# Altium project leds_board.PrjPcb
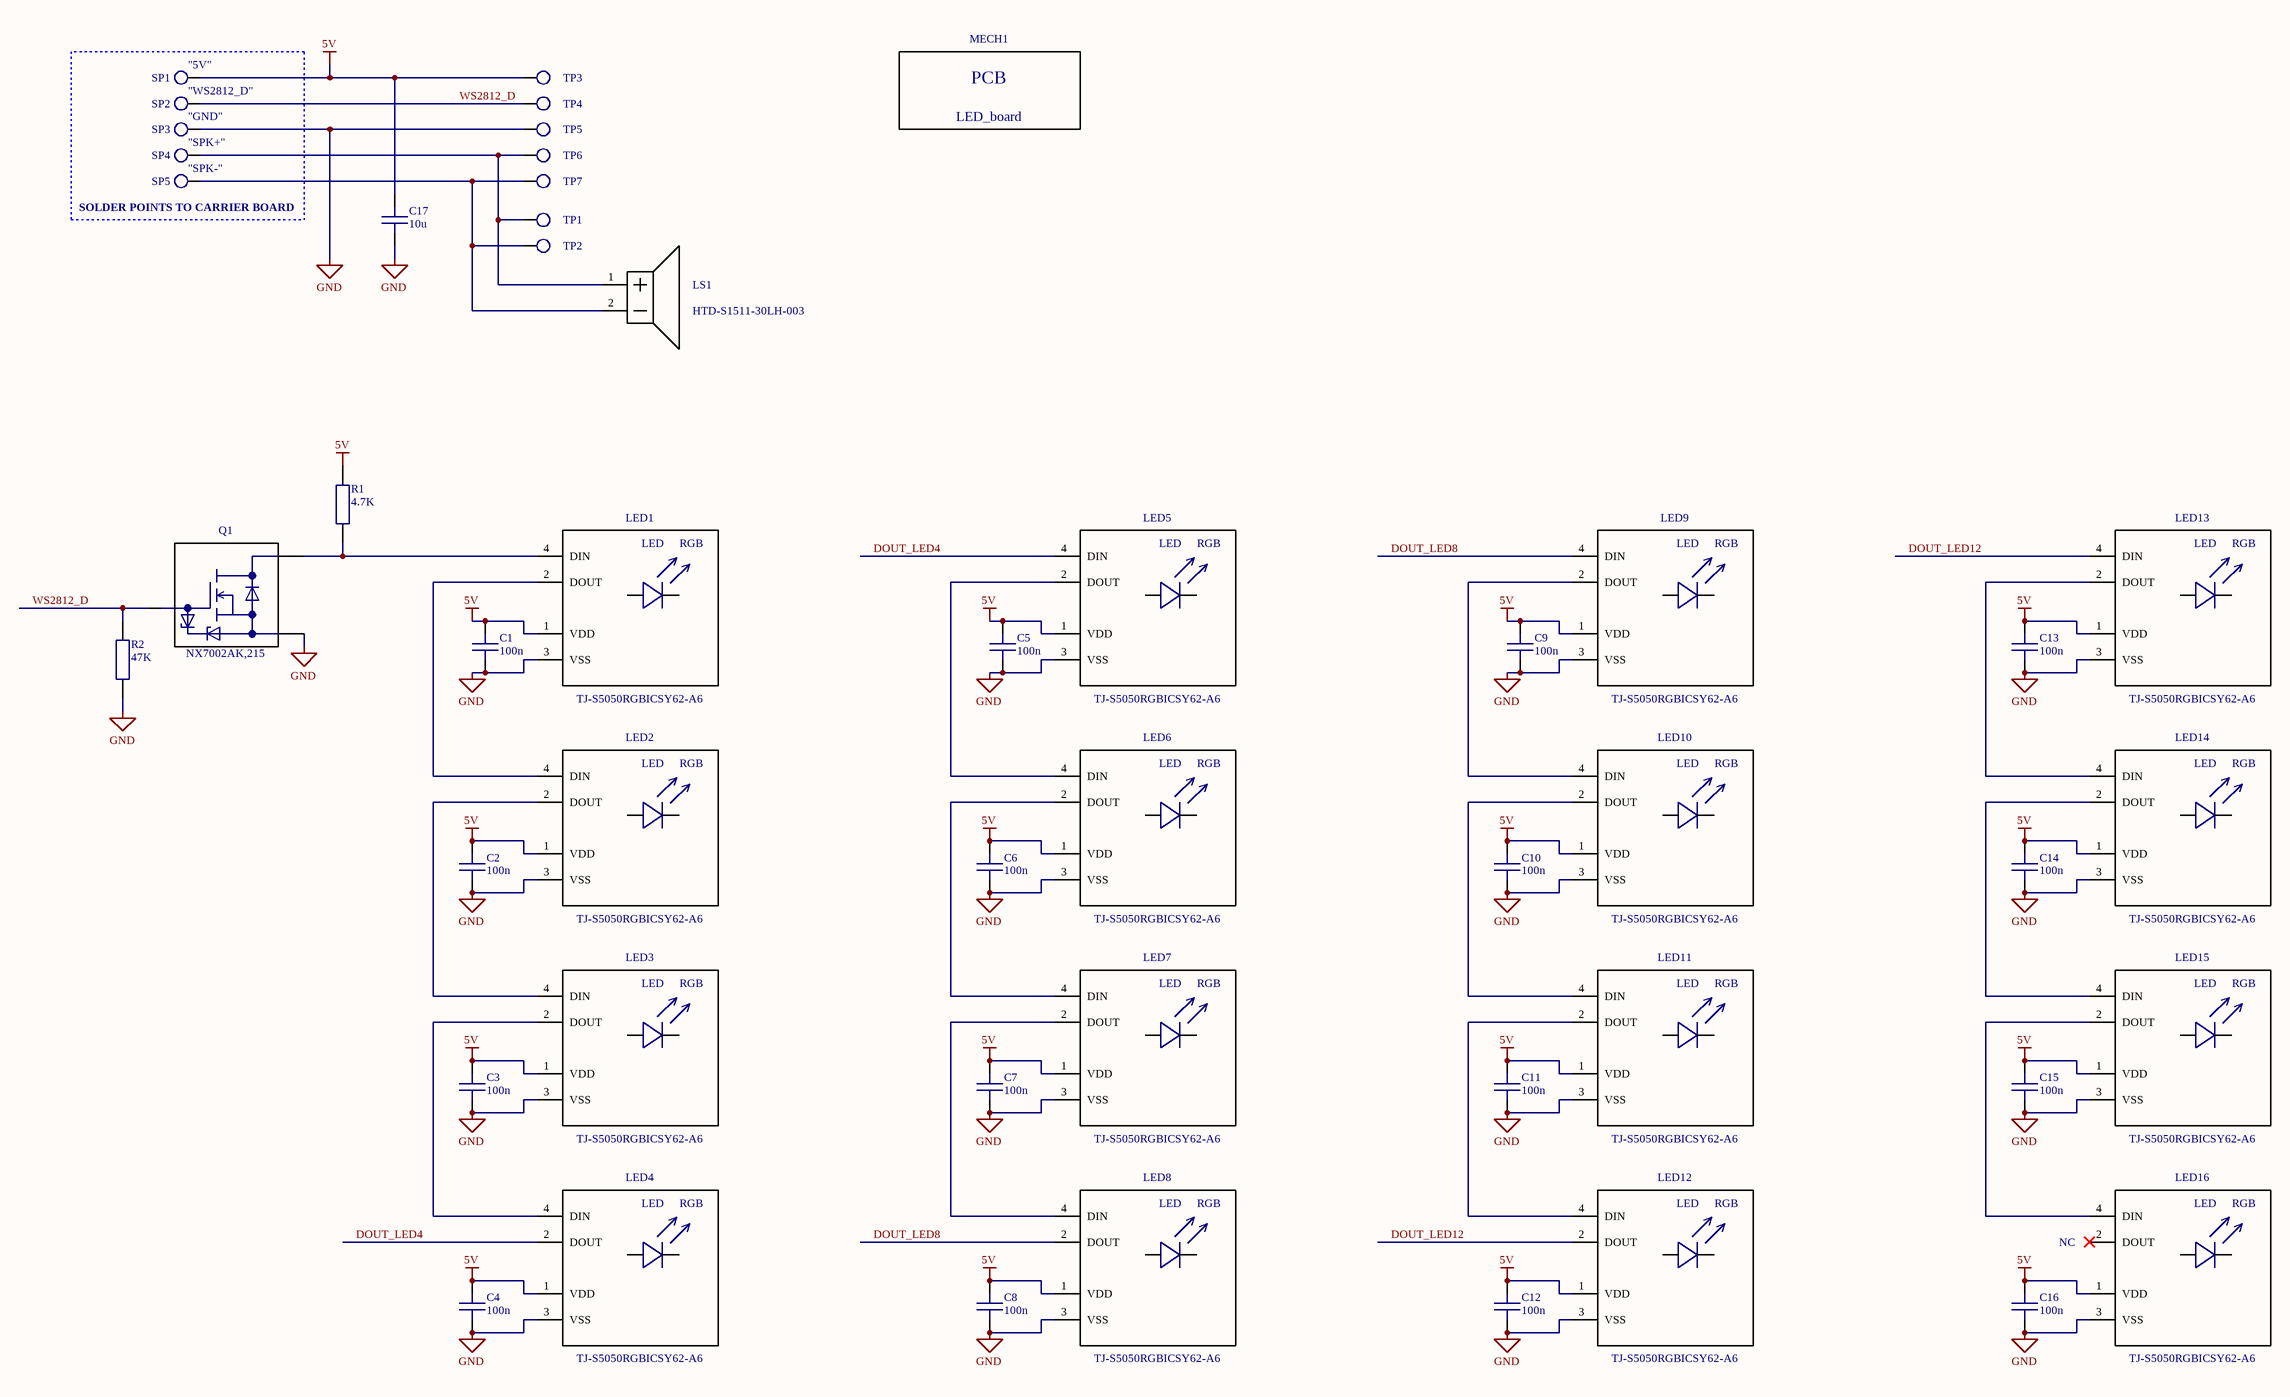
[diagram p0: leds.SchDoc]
1 sheet, 50 parts. Net scope: global (net labels, ports and power ports of the same name join across sheets).
Board file: leds.PcbDoc

## Sheet leds.SchDoc: LEDs
size A2; Project: RRRC; Reviewed: YES; Approved: YES; Author: AT; Engineer: AT; Organization: Softeq Development; Revision: 4.4; SheetNumber: 1; SheetTotal: 1

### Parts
C1  value 100n  [C_0402]  (hidden comment: CC0402KRX7R7BB104)
C2  value 100n  [C_0402]  (hidden comment: CC0402KRX7R7BB104)
C3  value 100n  [C_0402]  (hidden comment: CC0402KRX7R7BB104)
C4  value 100n  [C_0402]  (hidden comment: CC0402KRX7R7BB104)
C5  value 100n  [C_0402]  (hidden comment: CC0402KRX7R7BB104)
C6  value 100n  [C_0402]  (hidden comment: CC0402KRX7R7BB104)
C7  value 100n  [C_0402]  (hidden comment: CC0402KRX7R7BB104)
C8  value 100n  [C_0402]  (hidden comment: CC0402KRX7R7BB104)
C9  value 100n  [C_0402]  (hidden comment: CC0402KRX7R7BB104)
C10  value 100n  [C_0402]  (hidden comment: CC0402KRX7R7BB104)
C11  value 100n  [C_0402]  (hidden comment: CC0402KRX7R7BB104)
C12  value 100n  [C_0402]  (hidden comment: CC0402KRX7R7BB104)
C13  value 100n  [C_0402]  (hidden comment: CC0402KRX7R7BB104)
C14  value 100n  [C_0402]  (hidden comment: CC0402KRX7R7BB104)
C15  value 100n  [C_0402]  (hidden comment: CC0402KRX7R7BB104)
C16  value 100n  [C_0402]  (hidden comment: CC0402KRX7R7BB104)
C17  value 10u  [C_0805]  (hidden comment: CC0805KKX5R8BB106)
LED1  TJ-S5050RGBICSY62-A6  [TONGJIA_TJ-S5050RGBICSY62-A6]
LED2  TJ-S5050RGBICSY62-A6  [TONGJIA_TJ-S5050RGBICSY62-A6]
LED3  TJ-S5050RGBICSY62-A6  [TONGJIA_TJ-S5050RGBICSY62-A6]
LED4  TJ-S5050RGBICSY62-A6  [TONGJIA_TJ-S5050RGBICSY62-A6]
LED5  TJ-S5050RGBICSY62-A6  [TONGJIA_TJ-S5050RGBICSY62-A6]
LED6  TJ-S5050RGBICSY62-A6  [TONGJIA_TJ-S5050RGBICSY62-A6]
LED7  TJ-S5050RGBICSY62-A6  [TONGJIA_TJ-S5050RGBICSY62-A6]
LED8  TJ-S5050RGBICSY62-A6  [TONGJIA_TJ-S5050RGBICSY62-A6]
LED9  TJ-S5050RGBICSY62-A6  [TONGJIA_TJ-S5050RGBICSY62-A6]
LED10  TJ-S5050RGBICSY62-A6  [TONGJIA_TJ-S5050RGBICSY62-A6]
LED11  TJ-S5050RGBICSY62-A6  [TONGJIA_TJ-S5050RGBICSY62-A6]
LED12  TJ-S5050RGBICSY62-A6  [TONGJIA_TJ-S5050RGBICSY62-A6]
LED13  TJ-S5050RGBICSY62-A6  [TONGJIA_TJ-S5050RGBICSY62-A6]
LED14  TJ-S5050RGBICSY62-A6  [TONGJIA_TJ-S5050RGBICSY62-A6]
LED15  TJ-S5050RGBICSY62-A6  [TONGJIA_TJ-S5050RGBICSY62-A6]
LED16  TJ-S5050RGBICSY62-A6  [TONGJIA_TJ-S5050RGBICSY62-A6]
LS1  HTD-S1511-30LH-003  [SHENZHENTONGHUIDA_TECH_HTD-S1511-30LH-003]
MECH1  LED_board  (mechanical)
Q1  NX7002AK,215  [SOT-23-3]
R1  value 4.7K  [R_0402]  (hidden comment: RC0402FR-074K7L)
R2  value 47K  [R_0402]  (hidden comment: RC0402FR-0747KL)
SP1  "5V"  [THSP_0.8_1.4]  (no BOM)
SP2  "WS2812_D"  [THSP_0.8_1.4]  (no BOM)
SP3  "GND"  [THSP_0.8_1.4]  (no BOM)
SP4  "SPK+"  [THSP_0.8_1.4]  (no BOM)
SP5  "SPK-"  [THSP_0.8_1.4]  (no BOM)
TP1  (no value)  [SSP_1.5x3.0]  (no BOM)
TP2  (no value)  [SSP_1.5x3.0]  (no BOM)
TP3  (no value)  [STP_0.9]  (no BOM)
TP4  (no value)  [STP_0.9]  (no BOM)
TP5  (no value)  [STP_0.9]  (no BOM)
TP6  (no value)  [STP_0.9]  (no BOM)
TP7  (no value)  [STP_0.9]  (no BOM)

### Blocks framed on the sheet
SOLDER POINTS TO CARRIER BOARD: SP1-SP5

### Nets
5V: C1.2 C2.2 C3.2 C4.2 C5.2 C6.2 C7.2 C8.2 C9.2 C10.2 C11.2 C12.2 C13.2 C14.2 C15.2 C16.2 C17.2 LED1.1(VDD) LED2.1(VDD) LED3.1(VDD) LED4.1(VDD) LED5.1(VDD) LED6.1(VDD) LED7.1(VDD) LED8.1(VDD) LED9.1(VDD) LED10.1(VDD) LED11.1(VDD) LED12.1(VDD) LED13.1(VDD) LED14.1(VDD) LED15.1(VDD) LED16.1(VDD) R1.2 SP1.1 TP3.1
GND: C1.1 C2.1 C3.1 C4.1 C5.1 C6.1 C7.1 C8.1 C9.1 C10.1 C11.1 C12.1 C13.1 C14.1 C15.1 C16.1 C17.1 LED1.3(VSS) LED2.3(VSS) LED3.3(VSS) LED4.3(VSS) LED5.3(VSS) LED6.3(VSS) LED7.3(VSS) LED8.3(VSS) LED9.3(VSS) LED10.3(VSS) LED11.3(VSS) LED12.3(VSS) LED13.3(VSS) LED14.3(VSS) LED15.3(VSS) LED16.3(VSS) Q1.2(S) R2.1 SP3.1 TP5.1
DOUT_LED4: LED4.2(DOUT) LED5.4(DIN)
DOUT_LED8: LED8.2(DOUT) LED9.4(DIN)
DOUT_LED12: LED12.2(DOUT) LED13.4(DIN)
WS2812_D: Q1.1(G) R2.2 SP2.1 TP4.1
NetLED1_2: LED1.2(DOUT) LED2.4(DIN)
NetLED1_4: LED1.4(DIN) Q1.3(D) R1.1
NetLED2_2: LED2.2(DOUT) LED3.4(DIN)
NetLED3_2: LED3.2(DOUT) LED4.4(DIN)
NetLED5_2: LED5.2(DOUT) LED6.4(DIN)
NetLED6_2: LED6.2(DOUT) LED7.4(DIN)
NetLED7_2: LED7.2(DOUT) LED8.4(DIN)
NetLED9_2: LED9.2(DOUT) LED10.4(DIN)
NetLED10_2: LED10.2(DOUT) LED11.4(DIN)
NetLED11_2: LED11.2(DOUT) LED12.4(DIN)
NetLED13_2: LED13.2(DOUT) LED14.4(DIN)
NetLED14_2: LED14.2(DOUT) LED15.4(DIN)
NetLED15_2: LED15.2(DOUT) LED16.4(DIN)
NetLS1_1: LS1.1 SP4.1 TP1.1 TP6.1
NetLS1_2: LS1.2 SP5.1 TP2.1 TP7.1

Not connected (* = marked no-connect by the designer): LED16 2(DOUT)*

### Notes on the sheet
- NC

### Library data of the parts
C1-C16 = CC0402KRX7R7BB104: Capacitor, 100nF, 10%, 16V, X7R, -55/+125,0402; Manufacturer: Yageo
C17 = CC0805KKX5R8BB106: Capacitor, 10uF, 10%, 25V, X5R, -55/+85, 0805; Manufacturer: Yageo
LED1-LED16 = TJ-S5050RGBICSY62-A6: LED, RGB, 3.5-5.5V, SK6812 Serial Interface, 5050, -40/+85, SMD; Manufacturer: TAIWAN TONGJIA OPTOELECTRONICS TECHNOLOGY
LS1 = HTD-S1511-30LH-003: Speaker, magnetic, spring, 8 Ohm, 0.7W, 300Hz-20kHz, Top Rectangular, 85dB; Manufacturer: SHENZHENTONGHUIDA TECHNOLOGY; Mounted: No
MECH1 = GENERIC_PCB: PCB, Rev_4.4
Q1 = NX7002AK,215: MOSFET, N-CH, 60V, 190mA, -55/+150, TO-236AB; Manufacturer: Nexperia
R1 = RC0402FR-074K7L: Resistor, 4.7K, 1%, 0.063W, -55/+155, 0402; Manufacturer: Yageo
R2 = RC0402FR-0747KL: Resistor, 47K, 1%, 0.063W, -55/+155, 0402; Manufacturer: Yageo
SP1-SP5 = SolderPoint_TH_0.8x1.4: Solder Point, 0.8mm hole, 1.4mm pad, TH
TP1 TP2 = SolderPoint_1.5x3.0: Part Description: Solder Point, 1.5x3.0mm, SMD
TP3-TP7 = TestPoint_SMD_0.9: Part Description: Test Point, 0.9mm, SMD

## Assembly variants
NO_DNP_leds_board: not fitted CON1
